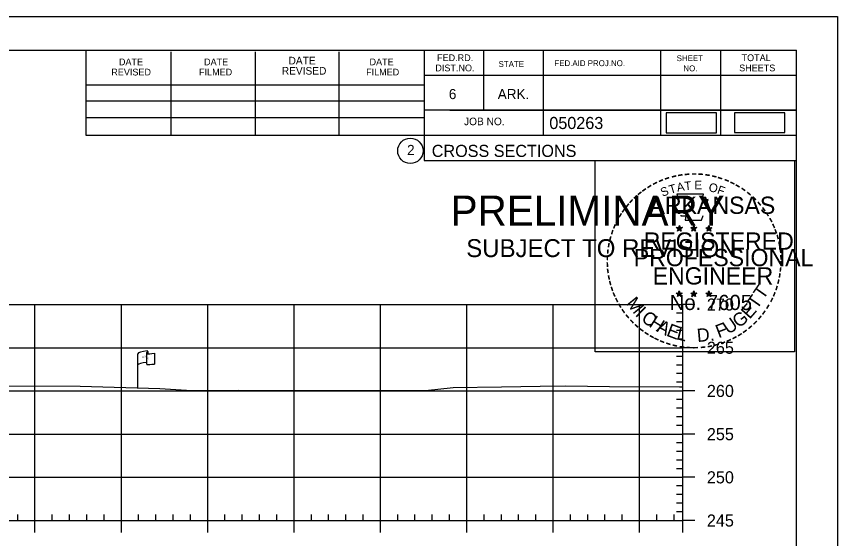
# Model space of a CAD drawing. Extents: x 1365647 to 1367999, y 387113 to 400173.
# Drawn here: x 1365961.9 to 1366057, y 387952.3 to 388012.7 of the extents above; entities that cross this region are included whole.
import ezdxf

# ---------------------------------------------------------------- set-up
doc = ezdxf.new("R2010")
doc.units = 0
for name, color, linetype in [('E_Existing ROW', 7, 'Continuous'), ('R_Axis', 7, 'Continuous'), ('R_Axis Annot', 7, 'Continuous'), ('R_Border', 7, 'Continuous'), ('R_Border PE', 7, 'Continuous'), ('R_Border Prem', 7, 'Continuous'), ('R_Detour', 7, 'Continuous'), ('R_Exist Surface', 7, 'Continuous'), ('R_Grid', 7, 'Continuous'), ('R_No Plot', 7, 'Continuous')]:
    doc.layers.add(name, color=color, linetype=linetype)

msp = doc.modelspace()

# ---------------------------------------------------------------- linework, layer by layer
at = {"layer": 'E_Existing ROW'}
for p, q in [((1365976.009, 387969.74), (1365976.009, 387973.691)), ((1365977.005, 387973.785), (1365977.005, 387973.772)), ((1365977.005, 387973.772), (1365977.005, 387972.545)), ((1365977.172, 387973.941), (1365977.172, 387973.701)), ((1365977.94, 387973.748), (1365977.94, 387972.508))]:
    msp.add_line(p, q, dxfattribs=at)
for centre, radius, start, end in [((1365977.094, 387973.941), 0.0783, 263.07118, 93.95638), ((1365977.083, 387973.786), 0.078, 88.6458, 274.28284), ((1365977.083, 387972.545), 0.0783, 180, 273.95638)]:
    msp.add_arc(centre, radius, start, end, dxfattribs=at)
for centre, major_axis, ratio, start_param, end_param in [((1365977.592, 387973.734), (-1.582, -0.043), 0.19887, 5.030368, 6.283185), ((1365978.299, 387973.85), (-1.227, -0.134), 0.052933, 0.159456, 1.268315), ((1365977.586, 387972.416), (-1.582, -0.043), 0.19887, 5.083035, 6.194897), ((1365978.299, 387972.61), (-1.227, -0.134), 0.052933, 0.159456, 1.268315)]:
    msp.add_ellipse(centre, major_axis=major_axis, ratio=ratio, start_param=start_param, end_param=end_param, dxfattribs=at)
at = {"layer": 'R_Axis'}
for p, q in [((1366039.095, 387954.393), (1366039.095, 387979.393)), ((1366040.495, 387979.393), (1366039.095, 387979.393)), ((1366039.095, 387978.393), (1366038.395, 387978.393)), ((1366039.095, 387977.393), (1366038.395, 387977.393)), ((1366039.095, 387976.393), (1366038.395, 387976.393)), ((1366039.095, 387975.393), (1366038.395, 387975.393)), ((1366040.495, 387974.393), (1366039.095, 387974.393)), ((1366039.095, 387973.393), (1366038.395, 387973.393)), ((1366039.095, 387972.393), (1366038.395, 387972.393)), ((1366039.095, 387971.393), (1366038.395, 387971.393)), ((1366039.095, 387970.393), (1366038.395, 387970.393)), ((1366040.495, 387969.393), (1366039.095, 387969.393)), ((1366039.095, 387968.393), (1366038.395, 387968.393)), ((1366039.095, 387967.393), (1366038.395, 387967.393)), ((1366039.095, 387966.393), (1366038.395, 387966.393)), ((1366039.095, 387965.393), (1366038.395, 387965.393)), ((1366040.495, 387964.393), (1366039.095, 387964.393)), ((1366039.095, 387963.393), (1366038.395, 387963.393)), ((1366039.095, 387962.393), (1366038.395, 387962.393)), ((1366039.095, 387961.393), (1366038.395, 387961.393)), ((1366039.095, 387960.393), (1366038.395, 387960.393)), ((1366040.495, 387959.393), (1366039.095, 387959.393)), ((1366039.095, 387958.393), (1366038.395, 387958.393)), ((1366039.095, 387957.393), (1366038.395, 387957.393)), ((1366039.095, 387956.393), (1366038.395, 387956.393)), ((1365962.095, 387954.393), (1365962.095, 387955.093)), ((1365966.095, 387954.393), (1365966.095, 387955.093)), ((1365968.095, 387954.393), (1365968.095, 387955.093)), ((1365970.095, 387954.393), (1365970.095, 387955.093)), ((1365972.095, 387954.393), (1365972.095, 387955.093)), ((1365976.095, 387954.393), (1365976.095, 387955.093)), ((1365978.095, 387954.393), (1365978.095, 387955.093)), ((1365980.095, 387954.393), (1365980.095, 387955.093)), ((1365982.095, 387954.393), (1365982.095, 387955.093)), ((1365986.095, 387954.393), (1365986.095, 387955.093)), ((1365988.095, 387954.393), (1365988.095, 387955.093)), ((1365990.095, 387954.393), (1365990.095, 387955.093)), ((1365992.095, 387954.393), (1365992.095, 387955.093)), ((1365996.095, 387954.393), (1365996.095, 387955.093)), ((1365998.095, 387954.393), (1365998.095, 387955.093)), ((1366000.095, 387954.393), (1366000.095, 387955.093)), ((1366002.095, 387954.393), (1366002.095, 387955.093)), ((1366006.095, 387954.393), (1366006.095, 387955.093)), ((1366008.095, 387954.393), (1366008.095, 387955.093)), ((1366010.095, 387954.393), (1366010.095, 387955.093)), ((1366012.095, 387954.393), (1366012.095, 387955.093)), ((1366016.095, 387954.393), (1366016.095, 387955.093)), ((1366018.095, 387954.393), (1366018.095, 387955.093)), ((1366020.095, 387954.393), (1366020.095, 387955.093)), ((1366022.095, 387954.393), (1366022.095, 387955.093)), ((1366026.095, 387954.393), (1366026.095, 387955.093)), ((1366028.095, 387954.393), (1366028.095, 387955.093)), ((1366030.095, 387954.393), (1366030.095, 387955.093)), ((1366032.095, 387954.393), (1366032.095, 387955.093)), ((1366036.095, 387954.393), (1366036.095, 387955.093)), ((1366038.095, 387954.393), (1366038.095, 387955.093)), ((1366039.095, 387955.393), (1366038.395, 387955.393)), ((1365749.095, 387954.393), (1366039.095, 387954.393)), ((1365964.095, 387952.993), (1365964.095, 387954.393)), ((1365974.095, 387952.993), (1365974.095, 387954.393)), ((1365984.095, 387952.993), (1365984.095, 387954.393)), ((1365994.095, 387952.993), (1365994.095, 387954.393)), ((1366004.095, 387952.993), (1366004.095, 387954.393)), ((1366014.095, 387952.993), (1366014.095, 387954.393)), ((1366024.095, 387952.993), (1366024.095, 387954.393)), ((1366034.095, 387952.993), (1366034.095, 387954.393)), ((1366039.095, 387952.993), (1366039.095, 387954.393)), ((1366040.495, 387954.393), (1366039.095, 387954.393))]:
    msp.add_line(p, q, dxfattribs=at)
at = {"layer": 'R_Border'}
for p, q in [((1365736.095, 388008.853), (1366052.275, 388008.853)), ((1365970.015, 387998.973), (1365970.015, 388008.853)), ((1365979.875, 387998.973), (1365979.875, 388008.653)), ((1365989.635, 387998.973), (1365989.635, 388008.653)), ((1365999.315, 387998.973), (1365999.315, 388008.653)), ((1366009.175, 388008.853), (1366009.175, 387996.053)), ((1366016.015, 388008.853), (1366016.015, 388001.913)), ((1366022.955, 388008.853), (1366022.955, 387998.973)), ((1366036.535, 388008.853), (1366036.535, 387998.973)), ((1366043.475, 388008.853), (1366043.475, 387998.973)), ((1366052.275, 387803.393), (1366052.275, 388008.853)), ((1366052.275, 388005.913), (1366009.175, 388005.913)), ((1366052.275, 388005.933), (1366052.275, 388005.933)), ((1365970.015, 388004.833), (1366009.175, 388004.833)), ((1365970.015, 388002.973), (1366009.175, 388002.973)), ((1366052.275, 388001.913), (1366009.175, 388001.913)), ((1366012.135, 388001.913), (1366052.275, 388001.913)), ((1365970.015, 387998.973), (1365970.015, 388001.033)), ((1365970.015, 388001.033), (1366009.175, 388001.033)), ((1366052.275, 387998.973), (1365970.015, 387998.973)), ((1366009.175, 387996.053), (1366052.275, 387996.053))]:
    msp.add_line(p, q, dxfattribs=at)
msp.add_circle((1366007.562, 387997.188), 1.467, dxfattribs=at)
at = {"layer": 'R_Border PE'}
for p, q in [((1366038.356, 387988.299), (1366038.705, 387988.188)), ((1366038.356, 387988.299), (1366038.609, 387988.254)), ((1366038.356, 387988.299), (1366038.593, 387988.177)), ((1366038.705, 387988.553), (1366038.664, 387988.301)), ((1366038.705, 387988.188), (1366038.705, 387988.553)), ((1366038.705, 387988.553), (1366038.754, 387988.303)), ((1366039.052, 387988.299), (1366038.705, 387988.188)), ((1366039.052, 387988.299), (1366038.766, 387988.25)), ((1366039.052, 387988.299), (1366038.848, 387988.197)), ((1366040.026, 387988.299), (1366040.375, 387988.188)), ((1366040.026, 387988.299), (1366040.279, 387988.254)), ((1366040.026, 387988.299), (1366040.263, 387988.177)), ((1366040.375, 387988.553), (1366040.334, 387988.301)), ((1366040.375, 387988.188), (1366040.375, 387988.553)), ((1366040.375, 387988.553), (1366040.424, 387988.303)), ((1366040.722, 387988.299), (1366040.375, 387988.188)), ((1366040.722, 387988.299), (1366040.436, 387988.25)), ((1366040.722, 387988.299), (1366040.518, 387988.197)), ((1366041.79, 387988.287), (1366042.139, 387988.176)), ((1366041.79, 387988.287), (1366042.043, 387988.242)), ((1366041.79, 387988.287), (1366042.027, 387988.165)), ((1366042.139, 387988.541), (1366042.098, 387988.289)), ((1366042.139, 387988.176), (1366042.139, 387988.541)), ((1366042.139, 387988.541), (1366042.188, 387988.291)), ((1366042.486, 387988.287), (1366042.139, 387988.176)), ((1366042.486, 387988.287), (1366042.2, 387988.238)), ((1366042.486, 387988.287), (1366042.282, 387988.185)), ((1366038.489, 387987.891), (1366038.705, 387988.188)), ((1366038.489, 387987.891), (1366038.615, 387988.135)), ((1366038.489, 387987.891), (1366038.703, 387988.108)), ((1366038.918, 387987.891), (1366038.703, 387988.105)), ((1366038.918, 387987.891), (1366038.705, 387988.188)), ((1366038.918, 387987.891), (1366038.781, 387988.182)), ((1366040.159, 387987.891), (1366040.375, 387988.188)), ((1366040.159, 387987.891), (1366040.285, 387988.135)), ((1366040.159, 387987.891), (1366040.373, 387988.108)), ((1366040.588, 387987.891), (1366040.373, 387988.105)), ((1366040.588, 387987.891), (1366040.375, 387988.188)), ((1366040.588, 387987.891), (1366040.451, 387988.182)), ((1366041.923, 387987.879), (1366042.139, 387988.176)), ((1366041.923, 387987.879), (1366042.049, 387988.123)), ((1366041.923, 387987.879), (1366042.137, 387988.096)), ((1366042.352, 387987.879), (1366042.137, 387988.093)), ((1366042.352, 387987.879), (1366042.139, 387988.176)), ((1366042.352, 387987.879), (1366042.215, 387988.17)), ((1366038.352, 387980.726), (1366038.701, 387980.615)), ((1366038.352, 387980.726), (1366038.605, 387980.681)), ((1366038.352, 387980.726), (1366038.589, 387980.604)), ((1366038.701, 387980.98), (1366038.66, 387980.728)), ((1366038.701, 387980.615), (1366038.701, 387980.98)), ((1366038.701, 387980.98), (1366038.75, 387980.73)), ((1366039.048, 387980.726), (1366038.701, 387980.615)), ((1366039.048, 387980.726), (1366038.762, 387980.677)), ((1366039.048, 387980.726), (1366038.844, 387980.624)), ((1366040.021, 387980.726), (1366040.37, 387980.615)), ((1366040.021, 387980.726), (1366040.274, 387980.681)), ((1366040.021, 387980.726), (1366040.258, 387980.604)), ((1366040.37, 387980.98), (1366040.329, 387980.728)), ((1366040.37, 387980.615), (1366040.37, 387980.98)), ((1366040.37, 387980.98), (1366040.419, 387980.73)), ((1366040.717, 387980.726), (1366040.37, 387980.615)), ((1366040.717, 387980.726), (1366040.431, 387980.677)), ((1366040.717, 387980.726), (1366040.513, 387980.624)), ((1366041.788, 387980.716), (1366042.137, 387980.605)), ((1366041.788, 387980.716), (1366042.041, 387980.671)), ((1366041.788, 387980.716), (1366042.025, 387980.594)), ((1366042.137, 387980.97), (1366042.096, 387980.718)), ((1366042.137, 387980.605), (1366042.137, 387980.97)), ((1366042.137, 387980.97), (1366042.186, 387980.72)), ((1366042.484, 387980.716), (1366042.137, 387980.605)), ((1366042.484, 387980.716), (1366042.198, 387980.667)), ((1366042.484, 387980.716), (1366042.28, 387980.614)), ((1366038.485, 387980.318), (1366038.701, 387980.615)), ((1366038.485, 387980.318), (1366038.611, 387980.562)), ((1366038.485, 387980.318), (1366038.699, 387980.535)), ((1366038.914, 387980.318), (1366038.699, 387980.532)), ((1366038.914, 387980.318), (1366038.701, 387980.615)), ((1366038.914, 387980.318), (1366038.777, 387980.609)), ((1366040.154, 387980.318), (1366040.37, 387980.615)), ((1366040.154, 387980.318), (1366040.28, 387980.562)), ((1366040.154, 387980.318), (1366040.368, 387980.535)), ((1366040.583, 387980.318), (1366040.368, 387980.532)), ((1366040.583, 387980.318), (1366040.37, 387980.615)), ((1366040.583, 387980.318), (1366040.446, 387980.609)), ((1366041.921, 387980.308), (1366042.137, 387980.605)), ((1366041.921, 387980.308), (1366042.047, 387980.552)), ((1366041.921, 387980.308), (1366042.135, 387980.525)), ((1366042.35, 387980.308), (1366042.135, 387980.522)), ((1366042.35, 387980.308), (1366042.137, 387980.605)), ((1366042.35, 387980.308), (1366042.213, 387980.599))]:
    msp.add_line(p, q, dxfattribs=at)
for points in [[(1366038.397, 387992.177), (1366038.666, 387991.35)], [(1366041.908, 387991.255), (1366042.05, 387991.539), (1366041.365, 387991.515), (1366041.513, 387992.177), (1366038.397, 387992.177)], [(1366038.889, 387989.754), (1366038.889, 387989.667), (1366039.452, 387989.648), (1366039.398, 387989.175), (1366041.268, 387989.175), (1366041.469, 387989.711)], [(1366038.705, 387988.553), (1366038.918, 387987.891), (1366038.356, 387988.299), (1366039.052, 387988.299), (1366038.489, 387987.891), (1366038.705, 387988.553)], [(1366040.375, 387988.553), (1366040.588, 387987.891), (1366040.026, 387988.299), (1366040.722, 387988.299), (1366040.159, 387987.891), (1366040.375, 387988.553)], [(1366042.139, 387988.541), (1366042.352, 387987.879), (1366041.79, 387988.287), (1366042.486, 387988.287), (1366041.923, 387987.879), (1366042.139, 387988.541)], [(1366038.701, 387980.98), (1366038.914, 387980.318), (1366038.352, 387980.726), (1366039.048, 387980.726), (1366038.485, 387980.318), (1366038.701, 387980.98)], [(1366040.37, 387980.98), (1366040.583, 387980.318), (1366040.021, 387980.726), (1366040.717, 387980.726), (1366040.154, 387980.318), (1366040.37, 387980.98)], [(1366042.137, 387980.97), (1366042.35, 387980.308), (1366041.788, 387980.716), (1366042.484, 387980.716), (1366041.921, 387980.308), (1366042.137, 387980.97)]]:
    msp.add_lwpolyline(points, dxfattribs=at)
for centre, radius in [((1366038.704, 387988.188), 0.172), ((1366038.704, 387988.188), 0.145), ((1366038.704, 387988.188), 0.116), ((1366038.704, 387988.188), 0.0991), ((1366038.704, 387988.188), 0.0747), ((1366040.374, 387988.188), 0.172), ((1366040.374, 387988.188), 0.145), ((1366040.374, 387988.188), 0.116), ((1366040.374, 387988.188), 0.0991), ((1366040.374, 387988.188), 0.0747), ((1366042.138, 387988.176), 0.172), ((1366042.138, 387988.176), 0.145), ((1366042.138, 387988.176), 0.116), ((1366042.138, 387988.176), 0.0991), ((1366042.138, 387988.176), 0.0747), ((1366038.704, 387988.188), 0.0495), ((1366038.704, 387988.188), 0.0296), ((1366040.374, 387988.188), 0.0495), ((1366040.374, 387988.188), 0.0296), ((1366042.138, 387988.176), 0.0495), ((1366042.138, 387988.176), 0.0296), ((1366038.7, 387980.615), 0.172), ((1366038.7, 387980.615), 0.145), ((1366038.7, 387980.615), 0.116), ((1366038.7, 387980.615), 0.0991), ((1366038.7, 387980.615), 0.0747), ((1366038.7, 387980.615), 0.0495), ((1366038.7, 387980.615), 0.0296), ((1366040.369, 387980.615), 0.172), ((1366040.369, 387980.615), 0.145), ((1366040.369, 387980.615), 0.116), ((1366040.369, 387980.615), 0.0991), ((1366040.369, 387980.615), 0.0747), ((1366040.369, 387980.615), 0.0495), ((1366040.369, 387980.615), 0.0296), ((1366042.136, 387980.605), 0.172), ((1366042.136, 387980.605), 0.145), ((1366042.136, 387980.605), 0.116), ((1366042.136, 387980.605), 0.0991), ((1366042.136, 387980.605), 0.0747), ((1366042.136, 387980.605), 0.0495), ((1366042.136, 387980.605), 0.0296)]:
    msp.add_circle(centre, radius, dxfattribs=at)
at = {"layer": 'R_Detour'}
for points in [[(1366037.165, 387999.272), (1366042.998, 387999.272), (1366042.998, 388001.583), (1366037.165, 388001.583)], [(1366045.079, 387999.296), (1366050.912, 387999.296), (1366050.912, 388001.606), (1366045.079, 388001.606)]]:
    msp.add_lwpolyline(points, close=True, dxfattribs=at)
at = {"layer": 'R_Exist Surface'}
msp.add_lwpolyline([(1365960.441, 387970.001), (1365969.334, 387969.958), (1365978.541, 387969.657), (1365982.24, 387969.443), (1365987.654, 387969.466), (1365998.482, 387969.45), (1366008.623, 387969.431), (1366009.173, 387969.432), (1366009.301, 387969.445), (1366012.533, 387969.797), (1366018.132, 387969.875), (1366022.583, 387969.965), (1366025.524, 387969.993), (1366030.617, 387969.922), (1366038.715, 387969.883), (1366039.095, 387969.881)], dxfattribs=at)
at = {"layer": 'R_Grid'}
for p, q in [((1365749.095, 387979.393), (1366039.095, 387979.393)), ((1365964.095, 387954.393), (1365964.095, 387979.393)), ((1365974.095, 387954.393), (1365974.095, 387979.393)), ((1365984.095, 387954.393), (1365984.095, 387979.393)), ((1365994.095, 387954.393), (1365994.095, 387979.393)), ((1366004.095, 387954.393), (1366004.095, 387979.393)), ((1366014.095, 387954.393), (1366014.095, 387979.393)), ((1366024.095, 387954.393), (1366024.095, 387979.393)), ((1366034.095, 387954.393), (1366034.095, 387979.393)), ((1366039.095, 387954.393), (1366039.095, 387979.393)), ((1365749.095, 387974.393), (1366039.095, 387974.393)), ((1365749.095, 387969.393), (1366039.095, 387969.393)), ((1365749.095, 387964.393), (1366039.095, 387964.393)), ((1365749.095, 387959.393), (1366039.095, 387959.393)), ((1365749.095, 387954.393), (1366039.095, 387954.393))]:
    msp.add_line(p, q, dxfattribs=at)
at = {"layer": 'R_No Plot'}
msp.add_line((1365723.694, 388012.747), (1366057.027, 388012.747), dxfattribs=at)
for points in [[(1365723.687, 388012.747), (1366057.027, 388012.747), (1366057.027, 387799.41), (1365723.687, 387799.41)], [(1366028.946, 387996.085), (1366052.044, 387996.085), (1366052.044, 387973.935), (1366028.946, 387973.935)]]:
    msp.add_lwpolyline(points, close=True, dxfattribs=at)

# ---------------------------------------------------------------- texts
at = {"layer": 'E_Existing ROW'}
for s, height, rotation, p in [('R ', 0.2, 9.98841, (1365976.529, 387973.192)), (' O', 0.2, 9.98841, (1365976.675, 387973.237)), ('W', 0.2, 351.17882, (1365977.005, 387973.068)), ('DWB 11-9-07', 0.001, 90, (1365977.172, 387973.701)), ('DWB 11-9-07', 0.001, 5.07169, (1365977.93, 387972.507)), ('DWB 11-9-07', 0.001, 90, (1365976.009, 387969.74))]:
    msp.add_text(s, height=height, rotation=rotation, dxfattribs=at).set_placement(p)
at = {"layer": 'R_Axis Annot'}
for s, p in [('270', (1366041.895, 387978.693)), ('265', (1366041.895, 387973.693)), ('260', (1366041.895, 387968.693)), ('255', (1366041.895, 387963.693)), ('250', (1366041.895, 387958.693)), ('245', (1366041.895, 387953.693))]:
    msp.add_text(s, height=1.4, dxfattribs=at).set_placement(p)
at = {"layer": 'R_Border'}
for s, height, p in [('FED.RD.', 0.7819, (1366010.655, 388007.573)), ('SHEET', 0.684, (1366038.395, 388007.573)), ('TOTAL', 0.7819, (1366045.915, 388007.573)), ('DATE', 0.7819, (1365973.815, 388007.093)), ('DATE', 0.7819, (1365983.675, 388007.093)), ('DATE', 0.8792, (1365993.455, 388007.193)), ('DATE', 0.7819, (1366002.835, 388007.093)), ('STATE', 0.684, (1366017.775, 388006.893)), ('FED.AID PROJ.NO.', 0.684, (1366024.235, 388006.993)), ('REVISED', 0.7819, (1365972.935, 388005.913)), ('FILMED', 0.7819, (1365983.095, 388005.913)), ('REVISED', 0.8792, (1365992.675, 388006.013)), ('FILMED', 0.7819, (1366002.435, 388005.913)), ('DIST.NO.', 0.7819, (1366010.455, 388006.393)), ('NO.', 0.684, (1366039.175, 388006.393)), ('SHEETS', 0.7819, (1366045.635, 388006.393)), ('6', 1.172, (1366012.015, 388003.173)), ('ARK.', 1.1723, (1366017.675, 388003.173)), ('JOB NO.', 0.8792, (1366013.775, 388000.153)), ('050263', 1.4, (1366023.651, 387999.712)), ('2', 1.172, (1366007.179, 387996.702)), ('CROSS SECTIONS', 1.4, (1366010.038, 387996.483))]:
    msp.add_text(s, height=height, rotation=360, dxfattribs=at).set_placement(p)
at = {"layer": 'R_Border PE'}
for s, height, rotation, p in [('-', 1.6, 19.17608, (1366037.145, 387993.304)), ('-', 1.6, 13.63015, (1366037.895, 387993.545)), ('-', 1.6, 10.21935, (1366038.573, 387993.707)), ('-', 1.6, 5.89682, (1366039.302, 387993.817)), ('-', 1.6, 0.18623, (1366040.074, 387993.889)), ('-', 1.6, 357.74304, (1366040.797, 387993.876)), ('-', 1.6, 352.16172, (1366041.541, 387993.82)), ('-', 1.6, 347.20489, (1366042.26, 387993.706)), ('-', 1.6, 342.3362, (1366042.895, 387993.551)), ('-', 1.6, 34.06357, (1366035.281, 387992.348)), ('-', 1.6, 28.79182, (1366035.878, 387992.718)), ('-', 1.6, 24.30721, (1366036.511, 387993.035)), ('S', 1, 21.59401, (1366036.752, 387991.855)), ('T', 1, 16.4036, (1366037.666, 387992.186)), ('A', 1, 11.21318, (1366038.492, 387992.437)), ('T', 1, 6.02276, (1366039.341, 387992.603)), ('E', 1, 0.83234, (1366040.446, 387992.713)), ('O', 1, 350.4515, (1366042.05, 387992.503)), ('F', 1, 340.07066, (1366043.004, 387992.275)), ('-', 1.6, 337.85509, (1366043.63, 387993.328)), ('-', 1.6, 334.12109, (1366044.261, 387993.057)), ('-', 1.6, 329.64089, (1366044.84, 387992.774)), ('-', 1.6, 42.96224, (1366033.794, 387991.158)), ('-', 1.6, 38.95066, (1366034.227, 387991.575)), ('-', 1.6, 36.23174, (1366034.703, 387991.953)), ('-', 1.6, 325.86266, (1366045.483, 387992.413)), ('-', 1.6, 320.52971, (1366046.093, 387991.987)), ('-', 1.6, 50.61417, (1366032.943, 387990.194)), ('-', 1.6, 48.42305, (1366033.346, 387990.68)), ('ARKANSAS', 2, 360, (1366035.25, 387989.889)), ('-', 1.6, 315.57859, (1366046.692, 387991.499)), ('-', 1.6, 309.87973, (1366047.261, 387990.949)), ('-', 1.6, 54.23247, (1366032.53, 387989.627)), ('-', 1.6, 306.65218, (1366047.786, 387990.347)), ('-', 1.6, 62.87135, (1366031.892, 387988.486)), ('-', 1.6, 58.07063, (1366032.205, 387989.1)), ('-', 1.4, 303.67529, (1366048.272, 387989.779)), ('-', 1.6, 299.66835, (1366048.591, 387989.172)), ('-', 1.6, 67.77427, (1366031.633, 387987.875)), ('-', 1.6, 294.66279, (1366048.915, 387988.56)), ('-', 1.6, 75.46096, (1366031.217, 387986.531)), ('-', 1.6, 72.39447, (1366031.414, 387987.245)), ('REGISTERED', 2, 360, (1366034.572, 387985.74)), ('DWB', 0.01, 360, (1366038.691, 387988.183)), ('DWB', 0.01, 360, (1366040.361, 387988.183)), ('DWB', 0.01, 360, (1366042.125, 387988.171)), ('-', 1.6, 290.57283, (1366049.172, 387987.983)), ('-', 1.6, 285.12326, (1366049.406, 387987.403)), ('-', 1.6, 81.20126, (1366031.085, 387985.818)), ('-', 1.6, 280.54934, (1366049.606, 387986.661)), ('-', 1.6, 85.18634, (1366031.009, 387985.127)), ('PROFESSIONAL', 2, 360, (1366033.424, 387983.836)), ('-', 1.6, 276.59616, (1366049.768, 387985.893)), ('-', 1.6, 89.06224, (1366030.984, 387984.426)), ('-', 1.6, 274.33011, (1366049.828, 387985.171)), ('-', 1.6, 269.94067, (1366049.862, 387984.539)), ('-', 1.6, 94.19588, (1366031.019, 387983.701)), ('-', 1.6, 98.94793, (1366031.091, 387983.034)), ('ENGINEER', 2, 360, (1366035.611, 387981.711)), ('-', 1.6, 263.5172, (1366049.843, 387983.873)), ('-', 1.6, 101.71495, (1366031.226, 387982.301)), ('-', 1.6, 260.99529, (1366049.772, 387983.219)), ('-', 1.6, 105.45785, (1366031.388, 387981.706)), ('T', 1.54, 55.05496, (1366048.42, 387979.88)), ('-', 1.6, 255.7626, (1366049.662, 387982.541)), ('-', 1.6, 109.08742, (1366031.603, 387981.075)), ('-', 1.6, 114.06432, (1366031.857, 387980.479)), ('-', 1.6, 247.88866, (1366049.258, 387981.148)), ('-', 1.6, 252.86809, (1366049.481, 387981.821)), ('-', 1.6, 115.72885, (1366032.162, 387979.861)), ('M', 1.54, 308.91747, (1366032.472, 387979.506)), ('No. 7605', 1.757, 360, (1366037.585, 387978.76)), ('DWB', 0.01, 360, (1366038.686, 387980.611)), ('DWB', 0.01, 360, (1366040.355, 387980.609)), ('DWB', 0.01, 360, (1366042.122, 387980.6)), ('T', 1.54, 55.05496, (1366047.689, 387978.76)), ('-', 1.6, 244.61971, (1366048.996, 387980.519)), ('-', 1.6, 120.44712, (1366032.519, 387979.275)), ('-', 1.6, 125.89344, (1366032.922, 387978.714)), ('I', 1.54, 316.46364, (1366033.514, 387978.186)), ('E', 1.54, 48.73133, (1366046.843, 387977.633)), ('-', 1.6, 239.07125, (1366048.602, 387979.767)), ('-', 1.6, 130.71812, (1366033.384, 387978.162)), ('C', 1.54, 324.01974, (1366034.187, 387977.563)), ('H', 1.54, 327.53419, (1366035.097, 387976.908)), ('U', 1.54, 34.40523, (1366044.391, 387975.88)), ('G', 1.54, 38.21734, (1366045.59, 387976.613)), ('-', 1.6, 231.25377, (1366047.77, 387978.548)), ('-', 1.6, 233.84524, (1366048.2, 387979.114)), ('-', 1.6, 134.22381, (1366033.901, 387977.617)), ('-', 1.6, 138.93382, (1366034.426, 387977.153)), ('A', 1.54, 332.55127, (1366035.951, 387976.371)), ('E', 1.54, 339.20679, (1366037.109, 387975.809)), ('L', 1.54, 346.2929, (1366038.301, 387975.385)), ('F', 1.54, 20.82016, (1366043.254, 387975.486)), ('-', 1.6, 221.08509, (1366046.769, 387977.475)), ('-', 1.6, 225.76533, (1366047.291, 387977.984)), ('-', 1.6, 144.64634, (1366034.982, 387976.747)), ('-', 1.6, 148.08978, (1366035.543, 387976.376)), ('D.', 1.54, 5.26016, (1366040.804, 387975.048)), ('-', 1.6, 212.24909, (1366045.686, 387976.616)), ('-', 1.6, 215.73633, (1366046.22, 387977.003)), ('-', 1.6, 151.57039, (1366036.122, 387976.051)), ('-', 1.6, 154.60019, (1366036.644, 387975.804)), ('-', 1.6, 158.56121, (1366037.268, 387975.55)), ('-', 1.6, 162.79826, (1366037.955, 387975.337)), ('-', 1.6, 200.71842, (1366043.885, 387975.678)), ('-', 1.6, 204.25161, (1366044.504, 387975.951)), ('-', 1.6, 207.35684, (1366045.128, 387976.27)), ('-', 1.6, 167.55551, (1366038.67, 387975.173)), ('-', 1.6, 173.11546, (1366039.442, 387975.063)), ('-', 1.6, 176.51827, (1366040.19, 387975.01)), ('-', 1.6, 181.59176, (1366040.934, 387975.029)), ('-', 1.6, 185.81666, (1366041.743, 387975.105)), ('-', 1.6, 191.28576, (1366042.479, 387975.237)), ('-', 1.6, 195.47429, (1366043.208, 387975.436))]:
    msp.add_text(s, height=height, rotation=rotation, dxfattribs=at).set_placement(p)
at = {"layer": 'R_Border Prem'}
for s, height, p in [('PRELIMINARY', 3.5, (1366012.226, 387988.516)), ('DWB', 0.01, (1366012.973, 387990.365)), ('SUBJECT TO REVISION', 2.07511, (1366014.035, 387984.887))]:
    msp.add_text(s, height=height, rotation=360, dxfattribs=at).set_placement(p)

doc.saveas('drawing.dxf')
